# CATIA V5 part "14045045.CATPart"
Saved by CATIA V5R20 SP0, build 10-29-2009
Part number: 14045045
Definition: NONE
Nomenclature: 14045045
Source: Unknown
Description: 14045045
Bounding box of the stored display mesh (mm): x -22.5 to 90, y -36.5 to 26.406, z -26.6 to 26.6
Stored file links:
  C:\Users\Utente\Desktop\IO LAVORO\3D X SITO CF\X SITO\PLASTICA\RF2\14045045.CATPart
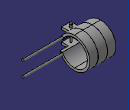
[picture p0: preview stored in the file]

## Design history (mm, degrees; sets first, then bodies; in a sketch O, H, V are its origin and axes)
Body1 "14045045" (main body)
  Solid1: solid without history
